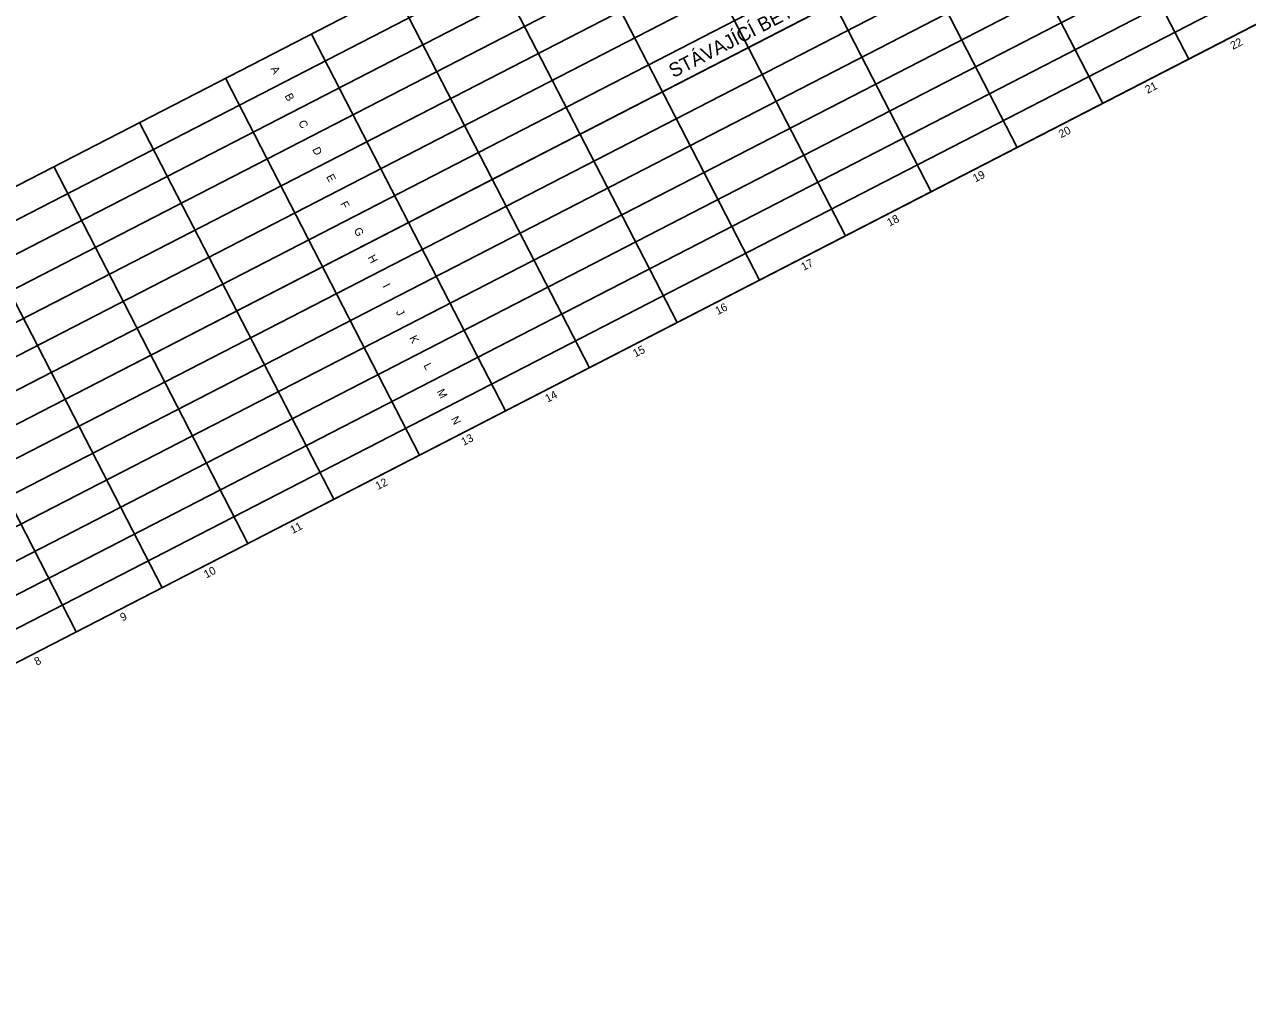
# Model space of a CAD drawing. Extents: x -886320 to -884760, y -1024172 to -1023483.
# Drawn here: x -885926.3 to -885773.4, y -1024171.6 to -1024051.4 of the extents above; entities that cross this region are included whole.
import ezdxf

# ---------------------------------------------------------------- set-up
doc = ezdxf.new("R2010")
doc.units = 0
for name, color, linetype in [('AGA__Netisknout', 7, 'Continuous'), ('Stavajici_betonova_draha', 7, 'Continuous'), ('Stavajici_betonova_draha_osa', 7, 'Continuous'), ('Stavajici_betonova_draha_popis', 7, 'Continuous'), ('Stavajici_betonova_draha_Popis desky', 7, 'Continuous'), ('Stavajici_betonova_draha_Spára', 7, 'Continuous')]:
    doc.layers.add(name, color=color, linetype=linetype)

msp = doc.modelspace()

# ---------------------------------------------------------------- linework, layer by layer
at = {"layer": 'AGA__Netisknout'}
msp.add_line((-886017.78, -1024147.99), (-884773.13, -1023507.02), dxfattribs=at)
at = {"layer": 'Stavajici_betonova_draha'}
for p, q in [((-886029.69, -1024124.32), (-884785.04, -1023483.35)), ((-886029.69, -1024124.32), (-884785.04, -1023483.35)), ((-886005.42, -1024171.44), (-884760.77, -1023530.47)), ((-886005.42, -1024171.44), (-884760.77, -1023530.47))]:
    msp.add_line(p, q, dxfattribs=at)
at = {"layer": 'Stavajici_betonova_draha_osa'}
msp.add_line((-886017.55, -1024147.88), (-884772.9, -1023506.91), dxfattribs=at)
at = {"layer": 'Stavajici_betonova_draha_Spára'}
for p, q in [((-886029.91, -1024124.43), (-884785.26, -1023483.46)), ((-886028.18, -1024127.8), (-884783.53, -1023486.82)), ((-886026.44, -1024131.16), (-884781.79, -1023490.19)), ((-886024.71, -1024134.53), (-884780.06, -1023493.56)), ((-886022.98, -1024137.89), (-884778.33, -1023496.92)), ((-886021.24, -1024141.26), (-884776.59, -1023500.29)), ((-886019.51, -1024144.63), (-884774.86, -1023503.65)), ((-886016.04, -1024151.36), (-884771.39, -1023510.39)), ((-886014.31, -1024154.72), (-884769.66, -1023513.75)), ((-886012.58, -1024158.09), (-884767.93, -1023517.12)), ((-886010.84, -1024161.46), (-884766.19, -1023520.48)), ((-886009.11, -1024164.82), (-884764.46, -1023523.85)), ((-886007.38, -1024168.19), (-884762.73, -1023527.21)), ((-886005.64, -1024171.55), (-884760.99, -1023530.58)), ((-885805.02, -1024008.62), (-885780.75, -1024055.74)), ((-885815.75, -1024014.14), (-885791.48, -1024061.27)), ((-885826.48, -1024019.67), (-885802.21, -1024066.79)), ((-885837.21, -1024025.19), (-885812.94, -1024072.32)), ((-885847.94, -1024030.72), (-885823.67, -1024077.84)), ((-885858.67, -1024036.25), (-885834.4, -1024083.37)), ((-885868.96, -1024041.55), (-885844.7, -1024088.67)), ((-885879.94, -1024047.2), (-885855.67, -1024094.32)), ((-885890.42, -1024052.6), (-885866.16, -1024099.72)), ((-885901.15, -1024058.12), (-885876.89, -1024105.25)), ((-885911.88, -1024063.65), (-885887.61, -1024110.77)), ((-885922.61, -1024069.17), (-885898.34, -1024116.3)), ((-885933.34, -1024074.7), (-885909.07, -1024121.82)), ((-885944.07, -1024080.23), (-885919.8, -1024127.35))]:
    msp.add_line(p, q, dxfattribs=at)

# ---------------------------------------------------------------- texts
at = {"layer": 'Stavajici_betonova_draha_popis'}
msp.add_text('STÁVAJÍCÍ BETONOVÁ DRÁHA 1400 × 53 m', height=1.75, rotation=27.2477, dxfattribs=at).set_placement((-885845.17, -1024058.12))
at = {"layer": 'Stavajici_betonova_draha_Popis desky'}
for s, rotation, p in [('22', 27.2477, (-885775.24, -1024054.59)), ('A', 297.2477, (-885895.54, -1024056.93)), ('B', 297.2477, (-885893.79, -1024060.32)), ('21', 27.2477, (-885785.9, -1024060.08)), ('C', 297.2477, (-885892.08, -1024063.66)), ('20', 27.2477, (-885796.7, -1024065.64)), ('D', 297.2477, (-885890.34, -1024067.03)), ('E', 297.2477, (-885888.59, -1024070.42)), ('19', 27.2477, (-885807.43, -1024071.17)), ('F', 297.2477, (-885886.85, -1024073.81)), ('18', 27.2477, (-885818.16, -1024076.69)), ('G', 297.2477, (-885885.15, -1024077.1)), ('H', 297.2477, (-885883.4, -1024080.51)), ('17', 27.2477, (-885828.89, -1024082.22)), ('I', 297.2477, (-885881.55, -1024084.1)), ('J', 297.2477, (-885879.88, -1024087.35)), ('16', 27.2477, (-885839.62, -1024087.74)), ('K', 297.2477, (-885878.21, -1024090.59)), ('15', 27.2477, (-885849.92, -1024093.05)), ('L', 297.2477, (-885876.43, -1024094.03)), ('M', 297.2477, (-885874.76, -1024097.28)), ('14', 27.2477, (-885860.89, -1024098.69)), ('N', 297.2477, (-885873, -1024100.7)), ('13', 27.2477, (-885871.38, -1024104.1)), ('12', 27.2477, (-885882.1, -1024109.62)), ('11', 27.2477, (-885892.76, -1024115.11)), ('10', 27.2477, (-885903.56, -1024120.67)), ('9', 27.2477, (-885914.01, -1024126.05)), ('8', 27.2477, (-885924.74, -1024131.58))]:
    msp.add_text(s, height=1, rotation=rotation, dxfattribs=at).set_placement(p)

doc.saveas('drawing.dxf')
